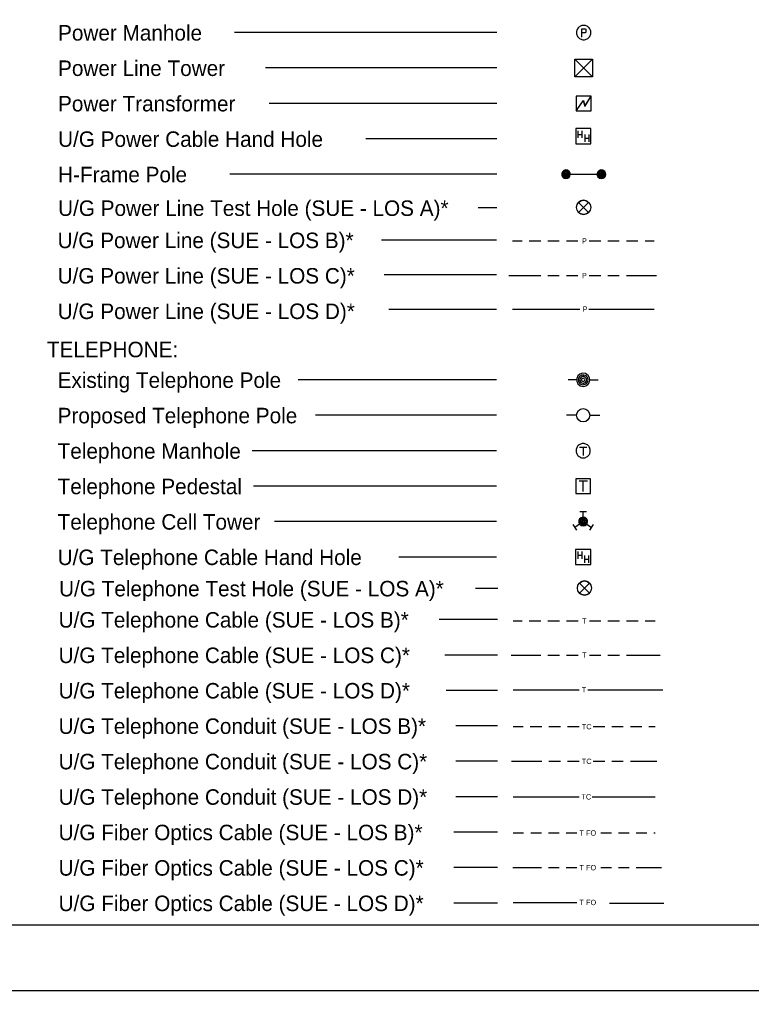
# Model space of a CAD drawing. Extents: x 1855058 to 1858918, y 1540202 to 1542502.
# Drawn here: x 1857985 to 1858402, y 1541402 to 1541955 of the extents above; entities that cross this region are included whole.
import ezdxf

# ---------------------------------------------------------------- set-up
doc = ezdxf.new("R2010")
doc.units = 0
for name, color, linetype in [('Default', 7, 'Continuous'), ('Exist Contamination Potential Cell', 7, 'Continuous'), ('Sheet Clip Boundary CELL', 7, 'Continuous'), ('Sheet Data Field CELL', 7, 'Continuous'), ('Sheet Summary Guardrail CELL', 7, 'Continuous'), ('Sheet Symbology CELL', 7, 'Continuous')]:
    doc.layers.add(name, color=color, linetype=linetype)

msp = doc.modelspace()

# ---------------------------------------------------------------- linework, layer by layer
at = {"layer": 'Default'}
msp.add_lwpolyline([(1857118.6, 1542501.77), (1857118.6, 1541401.77), (1858818.6, 1541401.77), (1858818.6, 1542501.77)], close=True, dxfattribs=at)
at = {"layer": 'Exist Contamination Potential Cell'}
msp.add_line((1857118.6, 1541401.77), (1858818.6, 1541401.77), dxfattribs=at)
at = {"layer": 'Sheet Clip Boundary CELL'}
for points in [[(1858309.22, 1541633.86), (1858303.52, 1541628.16), (1858306.37, 1541631.01), (1858303.52, 1541633.86), (1858309.22, 1541628.16)], [(1858303.52, 1541633.86), (1858306.37, 1541631.01), (1858309.22, 1541633.86)], [(1858309.22, 1541628.16), (1858306.37, 1541631.01), (1858303.52, 1541628.16)]]:
    msp.add_lwpolyline(points, dxfattribs=at)
msp.add_circle((1858306.37, 1541631.01), 4.03, dxfattribs=at)
for start, end in [(45, 135), (225, 315)]:
    msp.add_arc((1858306.37, 1541631.01), 4.03, start, end, dxfattribs=at)
at = {"layer": 'Sheet Data Field CELL'}
for p, q in [((1858307.06, 1541949.2), (1858307.06, 1541947.46)), ((1858256.47, 1541947.33), (1858106.98, 1541947.33)), ((1858306.74, 1541947.13), (1858304.9, 1541947.13)), ((1858310.98, 1541932.22), (1858300.9, 1541922.14)), ((1858310.98, 1541922.14), (1858300.9, 1541932.22)), ((1858256.47, 1541927.15), (1858124.63, 1541927.15)), ((1858256.47, 1541906.97), (1858126.68, 1541906.97)), ((1858302.61, 1541891.43), (1858302.61, 1541887.36)), ((1858302.61, 1541889.35), (1858304.94, 1541889.35)), ((1858304.94, 1541891.43), (1858304.94, 1541887.36)), ((1858306.49, 1541889.21), (1858306.49, 1541885.15)), ((1858306.49, 1541887.14), (1858308.82, 1541887.14)), ((1858308.82, 1541889.21), (1858308.82, 1541885.15)), ((1858256.47, 1541886.79), (1858181.91, 1541886.79)), ((1858256.47, 1541866.61), (1858104.43, 1541866.61)), ((1858295.83, 1541866.61), (1858316.01, 1541866.61)), ((1858256.47, 1541847.47), (1858245.73, 1541847.47)), ((1858256.19, 1541829.14), (1858190.69, 1541829.14)), ((1858265.28, 1541828.64), (1858270.83, 1541828.64)), ((1858274.87, 1541828.64), (1858281.43, 1541828.64)), ((1858285.46, 1541828.64), (1858292.02, 1541828.64)), ((1858296.06, 1541828.64), (1858302.61, 1541828.64)), ((1858309.07, 1541828.64), (1858315.63, 1541828.64)), ((1858319.66, 1541828.64), (1858326.22, 1541828.64)), ((1858330.26, 1541828.64), (1858336.82, 1541828.64)), ((1858340.85, 1541828.64), (1858346, 1541828.64)), ((1858256.19, 1541809.35), (1858192.24, 1541809.35)), ((1858263.24, 1541808.96), (1858281.43, 1541808.96)), ((1858285.46, 1541808.96), (1858292.02, 1541808.96)), ((1858296.06, 1541808.96), (1858302.61, 1541808.96)), ((1858309.07, 1541808.96), (1858315.63, 1541808.96)), ((1858319.66, 1541808.96), (1858326.22, 1541808.96)), ((1858330.26, 1541808.96), (1858347.44, 1541808.96)), ((1858256.19, 1541789.55), (1858194.96, 1541789.55)), ((1858265.28, 1541789.83), (1858303.71, 1541789.83)), ((1858308.76, 1541789.83), (1858346, 1541789.83)), ((1858256.19, 1541749.55), (1858143.3, 1541749.55)), ((1858301.92, 1541749.55), (1858297.08, 1541749.55)), ((1858309.37, 1541749.55), (1858314.21, 1541749.55)), ((1858256.19, 1541729.37), (1858153.22, 1541729.37)), ((1858301.89, 1541729.36), (1858296.22, 1541729.36)), ((1858309.46, 1541729.36), (1858315.14, 1541729.36)), ((1858307.74, 1541711.09), (1858303.58, 1541711.09)), ((1858305.64, 1541711.09), (1858305.64, 1541706.5)), ((1858256.19, 1541709.19), (1858117.1, 1541709.19)), ((1858256.19, 1541689.01), (1858117.8, 1541689.01)), ((1858303.28, 1541692.05), (1858308, 1541692.05)), ((1858305.64, 1541685.97), (1858305.64, 1541692.05)), ((1858303.75, 1541674.54), (1858307.53, 1541674.54)), ((1858305.64, 1541671.32), (1858305.64, 1541674.54)), ((1858256.19, 1541668.83), (1858129.85, 1541668.83)), ((1858302.06, 1541664.01), (1858299.88, 1541667.11)), ((1858303.61, 1541667.41), (1858300.97, 1541665.56)), ((1858307.68, 1541667.42), (1858310.32, 1541665.56)), ((1858311.4, 1541667.11), (1858309.23, 1541664.02)), ((1858302.55, 1541651.71), (1858302.55, 1541647.64)), ((1858302.55, 1541649.63), (1858304.87, 1541649.63)), ((1858304.87, 1541651.71), (1858304.87, 1541647.64)), ((1858306.43, 1541649.49), (1858306.43, 1541645.43)), ((1858308.75, 1541649.49), (1858308.75, 1541645.43)), ((1858256.19, 1541648.65), (1858200.66, 1541648.65)), ((1858306.43, 1541647.42), (1858308.75, 1541647.42)), ((1858257.02, 1541630.82), (1858244.25, 1541630.82)), ((1858256.74, 1541613.04), (1858223.67, 1541613.04)), ((1858265.83, 1541612.23), (1858270.9, 1541612.23)), ((1858274.94, 1541612.23), (1858281.5, 1541612.23)), ((1858285.53, 1541612.23), (1858292.09, 1541612.23)), ((1858296.13, 1541612.23), (1858302.69, 1541612.23)), ((1858309.14, 1541612.23), (1858315.7, 1541612.23)), ((1858319.74, 1541612.23), (1858326.29, 1541612.23)), ((1858330.33, 1541612.23), (1858336.89, 1541612.23)), ((1858340.92, 1541612.23), (1858346.55, 1541612.23)), ((1858256.74, 1541592.86), (1858226.85, 1541592.86)), ((1858264.57, 1541592.86), (1858281.5, 1541592.86)), ((1858285.53, 1541592.86), (1858292.09, 1541592.86)), ((1858296.13, 1541592.86), (1858302.69, 1541592.86)), ((1858309.14, 1541592.86), (1858315.7, 1541592.86)), ((1858319.74, 1541592.86), (1858326.29, 1541592.86)), ((1858330.33, 1541592.86), (1858349.54, 1541592.86)), ((1858256.74, 1541572.68), (1858227.63, 1541572.68)), ((1858265.83, 1541573.04), (1858303.29, 1541573.04)), ((1858308.34, 1541573.04), (1858351.09, 1541573.04)), ((1858256.74, 1541552.5), (1858233.07, 1541552.5)), ((1858265.83, 1541552.07), (1858271.47, 1541552.07)), ((1858275.51, 1541552.07), (1858282.07, 1541552.07)), ((1858286.1, 1541552.07), (1858292.66, 1541552.07)), ((1858296.7, 1541552.07), (1858303.25, 1541552.07)), ((1858311.32, 1541552.07), (1858317.88, 1541552.07)), ((1858321.92, 1541552.07), (1858328.48, 1541552.07)), ((1858332.51, 1541552.07), (1858339.07, 1541552.07)), ((1858343.11, 1541552.07), (1858346.55, 1541552.07)), ((1858256.74, 1541532.33), (1858233.07, 1541532.33)), ((1858264.87, 1541532.33), (1858282.07, 1541532.33)), ((1858286.1, 1541532.33), (1858292.66, 1541532.33)), ((1858296.7, 1541532.33), (1858303.25, 1541532.33)), ((1858311.32, 1541532.33), (1858317.88, 1541532.33)), ((1858321.92, 1541532.33), (1858328.48, 1541532.33)), ((1858332.51, 1541532.33), (1858347.52, 1541532.33)), ((1858256.74, 1541512.15), (1858233.07, 1541512.15)), ((1858265.83, 1541512.1), (1858303.25, 1541512.1)), ((1858310.82, 1541512.1), (1858346.55, 1541512.1)), ((1858256.74, 1541491.97), (1858231.9, 1541491.97)), ((1858265.83, 1541491.53), (1858271.72, 1541491.53)), ((1858275.76, 1541491.53), (1858281.81, 1541491.53)), ((1858285.85, 1541491.53), (1858291.9, 1541491.53)), ((1858295.94, 1541491.53), (1858301.99, 1541491.53)), ((1858315.61, 1541491.53), (1858321.67, 1541491.53)), ((1858325.7, 1541491.53), (1858331.76, 1541491.53)), ((1858335.79, 1541491.53), (1858341.85, 1541491.53)), ((1858345.88, 1541491.53), (1858346.55, 1541491.53)), ((1858256.74, 1541471.79), (1858231.9, 1541471.79)), ((1858265.65, 1541471.79), (1858281.81, 1541471.79)), ((1858285.85, 1541471.79), (1858291.9, 1541471.79)), ((1858295.94, 1541471.79), (1858301.99, 1541471.79)), ((1858315.61, 1541471.79), (1858321.67, 1541471.79)), ((1858325.7, 1541471.79), (1858331.76, 1541471.79)), ((1858335.79, 1541471.79), (1858350.23, 1541471.79)), ((1858256.74, 1541451.61), (1858231.9, 1541451.61)), ((1858265.83, 1541451.94), (1858302.03, 1541451.94)), ((1858320.69, 1541451.55), (1858351.59, 1541451.55))]:
    msp.add_line(p, q, dxfattribs=at)
for points in [[(1858305.92, 1541951.43), (1858305.39, 1541951.39), (1858304.9, 1541951.3), (1858304.41, 1541951.13), (1858303.95, 1541950.9), (1858303.52, 1541950.64), (1858303.13, 1541950.31), (1858302.77, 1541949.92), (1858302.47, 1541949.53), (1858302.21, 1541949.07), (1858302.05, 1541948.58), (1858301.92, 1541948.08), (1858301.85, 1541947.59), (1858301.85, 1541947.07), (1858301.92, 1541946.58), (1858302.05, 1541946.05), (1858302.21, 1541945.59), (1858302.47, 1541945.13), (1858302.77, 1541944.74), (1858303.13, 1541944.35), (1858303.52, 1541944.02), (1858303.95, 1541943.76), (1858304.41, 1541943.53), (1858304.9, 1541943.36), (1858305.42, 1541943.27), (1858305.92, 1541943.23), (1858306.44, 1541943.27), (1858306.93, 1541943.36), (1858307.42, 1541943.53), (1858307.88, 1541943.76), (1858308.31, 1541944.02), (1858308.7, 1541944.35), (1858309.06, 1541944.74), (1858309.36, 1541945.13), (1858309.62, 1541945.59), (1858309.78, 1541946.08), (1858309.91, 1541946.58), (1858309.98, 1541947.07), (1858309.98, 1541947.59), (1858309.91, 1541948.08), (1858309.78, 1541948.61), (1858309.62, 1541949.07), (1858309.36, 1541949.53), (1858309.06, 1541949.92), (1858308.7, 1541950.31), (1858308.31, 1541950.64), (1858307.88, 1541950.9), (1858307.42, 1541951.13), (1858306.93, 1541951.3), (1858306.41, 1541951.39), (1858305.92, 1541951.43)], [(1858304.9, 1541944.71), (1858304.9, 1541947.13), (1858304.9, 1541949.53), (1858306.74, 1541949.53)], [(1858306.74, 1541949.53), (1858306.87, 1541949.49), (1858306.96, 1541949.43), (1858307.03, 1541949.33), (1858307.06, 1541949.2)], [(1858307.06, 1541947.46), (1858307.03, 1541947.33), (1858306.96, 1541947.23), (1858306.87, 1541947.17), (1858306.74, 1541947.13)], [(1858310.98, 1541922.14), (1858300.9, 1541922.14), (1858300.9, 1541932.22), (1858310.98, 1541932.22), (1858310.98, 1541922.14), (1858300.9, 1541922.14), (1858300.9, 1541932.22), (1858310.98, 1541932.22), (1858310.98, 1541922.14)], [(1858301.71, 1541902.77), (1858305.68, 1541908.47), (1858306.65, 1541905.37), (1858310.12, 1541911.18)], [(1858301.71, 1541902.77), (1858305.72, 1541908.71), (1858306.62, 1541905.14), (1858310.12, 1541911.18)], [(1858301.71, 1541902.77), (1858310.12, 1541902.77), (1858310.12, 1541911.18), (1858301.71, 1541911.18), (1858301.71, 1541902.77)], [(1858301.36, 1541884.03), (1858310.05, 1541884.03), (1858310.05, 1541892.72), (1858301.36, 1541892.72), (1858301.36, 1541884.03)], [(1858297.66, 1541866.61), (1858297.61, 1541867.06), (1858297.46, 1541867.46), (1858297.22, 1541867.81), (1858296.92, 1541868.1), (1858296.57, 1541868.3), (1858296.12, 1541868.4), (1858295.73, 1541868.45), (1858295.28, 1541868.35), (1858294.88, 1541868.2), (1858294.59, 1541867.96), (1858294.29, 1541867.61), (1858294.09, 1541867.26), (1858293.99, 1541866.81), (1858293.99, 1541866.42), (1858294.09, 1541865.97), (1858294.29, 1541865.62), (1858294.59, 1541865.27), (1858294.88, 1541865.03), (1858295.28, 1541864.88), (1858295.73, 1541864.78), (1858296.12, 1541864.83), (1858296.57, 1541864.93), (1858296.92, 1541865.13), (1858297.22, 1541865.42), (1858297.46, 1541865.77), (1858297.61, 1541866.17), (1858297.66, 1541866.61)], [(1858297.07, 1541866.61), (1858297.02, 1541866.96), (1858296.87, 1541867.31), (1858296.62, 1541867.56), (1858296.32, 1541867.76), (1858296.03, 1541867.86), (1858295.63, 1541867.86), (1858295.33, 1541867.76), (1858295.03, 1541867.56), (1858294.78, 1541867.31), (1858294.64, 1541866.96), (1858294.59, 1541866.61), (1858294.64, 1541866.27), (1858294.78, 1541865.92), (1858295.03, 1541865.67), (1858295.33, 1541865.47), (1858295.63, 1541865.37), (1858296.03, 1541865.37), (1858296.32, 1541865.47), (1858296.62, 1541865.67), (1858296.87, 1541865.92), (1858297.02, 1541866.27), (1858297.07, 1541866.61)], [(1858296.42, 1541866.61), (1858296.37, 1541866.86), (1858296.22, 1541867.06), (1858296.03, 1541867.16), (1858295.78, 1541867.21), (1858295.53, 1541867.11), (1858295.33, 1541866.96), (1858295.23, 1541866.71), (1858295.23, 1541866.51), (1858295.33, 1541866.27), (1858295.53, 1541866.12), (1858295.78, 1541866.02), (1858296.03, 1541866.07), (1858296.22, 1541866.17), (1858296.37, 1541866.37), (1858296.42, 1541866.61)], [(1858317.84, 1541866.61), (1858317.79, 1541867.06), (1858317.64, 1541867.46), (1858317.4, 1541867.81), (1858317.1, 1541868.1), (1858316.75, 1541868.3), (1858316.3, 1541868.4), (1858315.91, 1541868.45), (1858315.46, 1541868.35), (1858315.06, 1541868.2), (1858314.76, 1541867.96), (1858314.47, 1541867.61), (1858314.27, 1541867.26), (1858314.17, 1541866.81), (1858314.17, 1541866.42), (1858314.27, 1541865.97), (1858314.47, 1541865.62), (1858314.76, 1541865.27), (1858315.06, 1541865.03), (1858315.46, 1541864.88), (1858315.91, 1541864.78), (1858316.3, 1541864.83), (1858316.75, 1541864.93), (1858317.1, 1541865.13), (1858317.4, 1541865.42), (1858317.64, 1541865.77), (1858317.79, 1541866.17), (1858317.84, 1541866.61)], [(1858317.25, 1541866.61), (1858317.2, 1541866.96), (1858317.05, 1541867.31), (1858316.8, 1541867.56), (1858316.5, 1541867.76), (1858316.2, 1541867.86), (1858315.81, 1541867.86), (1858315.51, 1541867.76), (1858315.21, 1541867.56), (1858314.96, 1541867.31), (1858314.81, 1541866.96), (1858314.76, 1541866.61), (1858314.81, 1541866.27), (1858314.96, 1541865.92), (1858315.21, 1541865.67), (1858315.51, 1541865.47), (1858315.81, 1541865.37), (1858316.2, 1541865.37), (1858316.5, 1541865.47), (1858316.8, 1541865.67), (1858317.05, 1541865.92), (1858317.2, 1541866.27), (1858317.25, 1541866.61)], [(1858316.6, 1541866.61), (1858316.55, 1541866.86), (1858316.4, 1541867.06), (1858316.2, 1541867.16), (1858315.96, 1541867.21), (1858315.71, 1541867.11), (1858315.51, 1541866.96), (1858315.41, 1541866.71), (1858315.41, 1541866.51), (1858315.51, 1541866.27), (1858315.71, 1541866.12), (1858315.96, 1541866.02), (1858316.2, 1541866.07), (1858316.4, 1541866.17), (1858316.55, 1541866.37), (1858316.6, 1541866.61)], [(1858308.4, 1541749.55), (1858308.32, 1541750.22), (1858308.1, 1541750.81), (1858307.73, 1541751.34), (1858307.28, 1541751.78), (1858306.76, 1541752.08), (1858306.09, 1541752.23), (1858305.49, 1541752.31), (1858304.82, 1541752.15), (1858304.22, 1541751.93), (1858303.78, 1541751.56), (1858303.33, 1541751.04), (1858303.03, 1541750.52), (1858302.88, 1541749.85), (1858302.88, 1541749.25), (1858303.03, 1541748.58), (1858303.33, 1541748.06), (1858303.78, 1541747.54), (1858304.22, 1541747.16), (1858304.82, 1541746.94), (1858305.49, 1541746.79), (1858306.09, 1541746.87), (1858306.76, 1541747.01), (1858307.28, 1541747.31), (1858307.73, 1541747.76), (1858308.1, 1541748.28), (1858308.32, 1541748.88), (1858308.4, 1541749.55)], [(1858307.5, 1541749.55), (1858307.43, 1541750.07), (1858307.2, 1541750.59), (1858306.83, 1541750.96), (1858306.39, 1541751.26), (1858305.94, 1541751.41), (1858305.34, 1541751.41), (1858304.89, 1541751.26), (1858304.45, 1541750.96), (1858304.08, 1541750.59), (1858303.85, 1541750.07), (1858303.78, 1541749.55), (1858303.85, 1541749.03), (1858304.08, 1541748.51), (1858304.45, 1541748.13), (1858304.89, 1541747.83), (1858305.34, 1541747.69), (1858305.94, 1541747.69), (1858306.39, 1541747.83), (1858306.83, 1541748.13), (1858307.2, 1541748.51), (1858307.43, 1541749.03), (1858307.5, 1541749.55)], [(1858306.53, 1541749.55), (1858306.46, 1541749.92), (1858306.24, 1541750.22), (1858305.94, 1541750.37), (1858305.57, 1541750.44), (1858305.19, 1541750.29), (1858304.89, 1541750.07), (1858304.75, 1541749.7), (1858304.75, 1541749.4), (1858304.89, 1541749.03), (1858305.19, 1541748.8), (1858305.57, 1541748.65), (1858305.94, 1541748.73), (1858306.24, 1541748.88), (1858306.46, 1541749.18), (1858306.53, 1541749.55)], [(1858305.64, 1541713.29), (1858305.12, 1541713.25), (1858304.63, 1541713.16), (1858304.13, 1541712.99), (1858303.67, 1541712.76), (1858303.25, 1541712.5), (1858302.86, 1541712.17), (1858302.49, 1541711.78), (1858302.2, 1541711.39), (1858301.94, 1541710.93), (1858301.77, 1541710.44), (1858301.64, 1541709.94), (1858301.58, 1541709.45), (1858301.58, 1541708.93), (1858301.64, 1541708.44), (1858301.77, 1541707.91), (1858301.94, 1541707.45), (1858302.2, 1541706.99), (1858302.49, 1541706.6), (1858302.86, 1541706.21), (1858303.25, 1541705.88), (1858303.67, 1541705.62), (1858304.13, 1541705.39), (1858304.63, 1541705.22), (1858305.15, 1541705.13), (1858305.64, 1541705.09), (1858306.16, 1541705.13), (1858306.66, 1541705.22), (1858307.15, 1541705.39), (1858307.61, 1541705.62), (1858308.03, 1541705.88), (1858308.43, 1541706.21), (1858308.79, 1541706.6), (1858309.08, 1541706.99), (1858309.34, 1541707.45), (1858309.51, 1541707.94), (1858309.64, 1541708.44), (1858309.7, 1541708.93), (1858309.7, 1541709.45), (1858309.64, 1541709.94), (1858309.51, 1541710.47), (1858309.34, 1541710.93), (1858309.08, 1541711.39), (1858308.79, 1541711.78), (1858308.43, 1541712.17), (1858308.03, 1541712.5), (1858307.61, 1541712.76), (1858307.15, 1541712.99), (1858306.66, 1541713.16), (1858306.13, 1541713.25), (1858305.64, 1541713.29)], [(1858301.39, 1541684.77), (1858309.89, 1541684.77), (1858309.89, 1541693.26), (1858301.39, 1541693.26), (1858301.39, 1541684.77)], [(1858307.48, 1541668.83), (1858307.43, 1541669.28), (1858307.28, 1541669.68), (1858307.03, 1541670.02), (1858306.73, 1541670.32), (1858306.39, 1541670.52), (1858305.94, 1541670.62), (1858305.54, 1541670.67), (1858305.09, 1541670.57), (1858304.7, 1541670.42), (1858304.4, 1541670.17), (1858304.1, 1541669.83), (1858303.9, 1541669.48), (1858303.8, 1541669.03), (1858303.8, 1541668.63), (1858303.9, 1541668.19), (1858304.1, 1541667.84), (1858304.4, 1541667.49), (1858304.7, 1541667.24), (1858305.09, 1541667.09), (1858305.54, 1541666.99), (1858305.94, 1541667.05), (1858306.39, 1541667.14), (1858306.73, 1541667.34), (1858307.03, 1541667.64), (1858307.28, 1541667.99), (1858307.43, 1541668.39), (1858307.48, 1541668.83)], [(1858306.88, 1541668.83), (1858306.83, 1541669.18), (1858306.68, 1541669.53), (1858306.43, 1541669.78), (1858306.14, 1541669.98), (1858305.84, 1541670.07), (1858305.44, 1541670.07), (1858305.14, 1541669.98), (1858304.85, 1541669.78), (1858304.6, 1541669.53), (1858304.45, 1541669.18), (1858304.4, 1541668.83), (1858304.45, 1541668.48), (1858304.6, 1541668.14), (1858304.85, 1541667.89), (1858305.14, 1541667.69), (1858305.44, 1541667.59), (1858305.84, 1541667.59), (1858306.14, 1541667.69), (1858306.43, 1541667.89), (1858306.68, 1541668.14), (1858306.83, 1541668.48), (1858306.88, 1541668.83)], [(1858306.24, 1541668.83), (1858306.19, 1541669.08), (1858306.04, 1541669.28), (1858305.84, 1541669.38), (1858305.59, 1541669.43), (1858305.34, 1541669.33), (1858305.14, 1541669.18), (1858305.04, 1541668.93), (1858305.04, 1541668.73), (1858305.14, 1541668.48), (1858305.34, 1541668.34), (1858305.59, 1541668.24), (1858305.84, 1541668.29), (1858306.04, 1541668.39), (1858306.19, 1541668.58), (1858306.24, 1541668.83)], [(1858301.3, 1541644.31), (1858309.98, 1541644.31), (1858309.98, 1541653), (1858301.3, 1541653), (1858301.3, 1541644.31)]]:
    msp.add_lwpolyline(points, dxfattribs=at)
for points in [[(1858295.83, 1541864.13), (1858296.87, 1541864.33), (1858297.56, 1541864.83), (1858298.11, 1541865.52), (1858298.31, 1541866.47), (1858298.21, 1541867.36), (1858297.71, 1541868.25), (1858296.72, 1541869), (1858295.58, 1541869.1), (1858294.59, 1541868.8), (1858293.79, 1541868.1), (1858293.39, 1541867.16), (1858293.39, 1541866.07), (1858293.79, 1541865.13), (1858294.68, 1541864.38)], [(1858316.01, 1541864.13), (1858317.05, 1541864.33), (1858317.74, 1541864.83), (1858318.29, 1541865.52), (1858318.49, 1541866.47), (1858318.39, 1541867.36), (1858317.89, 1541868.25), (1858316.9, 1541869), (1858315.76, 1541869.1), (1858314.76, 1541868.8), (1858313.97, 1541868.1), (1858313.57, 1541867.16), (1858313.57, 1541866.07), (1858313.97, 1541865.13), (1858314.86, 1541864.38)], [(1858305.64, 1541745.82), (1858307.2, 1541746.12), (1858308.25, 1541746.87), (1858309.07, 1541747.91), (1858309.37, 1541749.32), (1858309.22, 1541750.67), (1858308.47, 1541752), (1858306.98, 1541753.12), (1858305.27, 1541753.27), (1858303.78, 1541752.82), (1858302.59, 1541751.78), (1858301.99, 1541750.37), (1858301.99, 1541748.73), (1858302.59, 1541747.31), (1858303.93, 1541746.19)], [(1858305.64, 1541666.35), (1858306.68, 1541666.55), (1858307.38, 1541667.05), (1858307.93, 1541667.74), (1858308.12, 1541668.68), (1858308.02, 1541669.58), (1858307.53, 1541670.47), (1858306.54, 1541671.22), (1858305.39, 1541671.32), (1858304.4, 1541671.02), (1858303.61, 1541670.32), (1858303.21, 1541669.38), (1858303.21, 1541668.29), (1858303.61, 1541667.34), (1858304.5, 1541666.6)]]:
    msp.add_lwpolyline(points, close=True, dxfattribs=at)
msp.add_circle((1858305.64, 1541729.37), 3.78, dxfattribs=at)
at = {"layer": 'Sheet Summary Guardrail CELL'}
for points in [[(1858308.74, 1541850.63), (1858303.04, 1541844.93), (1858305.89, 1541847.78), (1858303.04, 1541850.63), (1858308.74, 1541844.93)], [(1858303.04, 1541850.63), (1858305.89, 1541847.78), (1858308.74, 1541850.63)], [(1858308.74, 1541844.93), (1858305.89, 1541847.78), (1858303.04, 1541844.93)]]:
    msp.add_lwpolyline(points, dxfattribs=at)
msp.add_circle((1858305.89, 1541847.78), 4.03, dxfattribs=at)
for start, end in [(45, 135), (225, 315)]:
    msp.add_arc((1858305.89, 1541847.78), 4.03, start, end, dxfattribs=at)
at = {"layer": 'Sheet Symbology CELL'}
msp.add_line((1857156.1, 1541439.27), (1858781.08, 1541439.27), dxfattribs=at)

# ---------------------------------------------------------------- texts
at = {"layer": 'Sheet Data Field CELL'}
for s, height, p in [('Power Manhole', 8.8282, (1858006.53, 1541942.75)), ('Power Line Tower', 8.8282, (1858006.53, 1541922.59)), ('Power Transformer', 8.8282, (1858006.51, 1541902.41)), ('U/G Power Cable Hand Hole', 8.8282, (1858006.54, 1541882.22)), ('H-Frame Pole', 8.8282, (1858006.54, 1541862.04)), ('U/G Power Line Test Hole (SUE - LOS A)*', 8.8282, (1858006.54, 1541842.89)), ('U/G Power Line (SUE - LOS B)*', 8.8282, (1858006.26, 1541824.56)), ('P', 3.03, (1858304.93, 1541827.13)), ('U/G Power Line (SUE - LOS C)*', 8.8282, (1858006.29, 1541804.37)), ('P', 3.03, (1858304.93, 1541807.45)), ('U/G Power Line (SUE - LOS D)*', 8.8282, (1858006.31, 1541784.18)), ('P', 3.03, (1858305.33, 1541788.32)), ('TELEPHONE:', 8.828, (1858000.15, 1541762.41)), ('Existing Telephone Pole', 8.8282, (1858006.26, 1541744.97)), ('Proposed Telephone Pole', 8.8282, (1858006.26, 1541724.79)), ('Telephone Manhole', 8.8282, (1858006.26, 1541704.61)), ('Telephone Pedestal', 8.8282, (1858006.26, 1541684.43)), ('Telephone Cell Tower', 8.8282, (1858006.28, 1541664.25)), ('U/G Telephone Cable Hand Hole', 8.8282, (1858006.28, 1541644.08)), ('U/G Telephone Test Hole (SUE - LOS A)*', 8.8282, (1858007.1, 1541626.24)), ('U/G Telephone Cable (SUE - LOS B)*', 8.8282, (1858006.83, 1541608.46)), ('T', 3.03, (1858304.96, 1541610.72)), ('U/G Telephone Cable (SUE - LOS C)*', 8.8282, (1858006.83, 1541588.28)), ('T', 3.03, (1858304.96, 1541591.35)), ('U/G Telephone Cable (SUE - LOS D)*', 8.8282, (1858006.83, 1541568.1)), ('T', 3.03, (1858304.85, 1541571.52)), ('U/G Telephone Conduit (SUE - LOS B)*', 8.8282, (1858006.83, 1541547.93)), ('TC', 3.027, (1858304.87, 1541550.56)), ('U/G Telephone Conduit (SUE - LOS C)*', 8.8282, (1858006.83, 1541527.75)), ('TC', 3.027, (1858304.87, 1541530.81)), ('U/G Telephone Conduit (SUE - LOS D)*', 8.8282, (1858006.83, 1541507.57)), ('TC', 3.027, (1858304.62, 1541510.58)), ('U/G Fiber Optics Cable (SUE - LOS B)*', 8.8282, (1858006.83, 1541487.39)), ('T FO', 3.027, (1858303.51, 1541490.01)), ('U/G Fiber Optics Cable (SUE - LOS C)*', 8.8282, (1858006.83, 1541467.21)), ('T FO', 3.027, (1858303.51, 1541470.28)), ('U/G Fiber Optics Cable (SUE - LOS D)*', 8.8282, (1858006.83, 1541447.03)), ('T FO', 3.027, (1858303.54, 1541450.43))]:
    msp.add_text(s, height=height, dxfattribs=at).set_placement(p)

doc.saveas('drawing.dxf')
